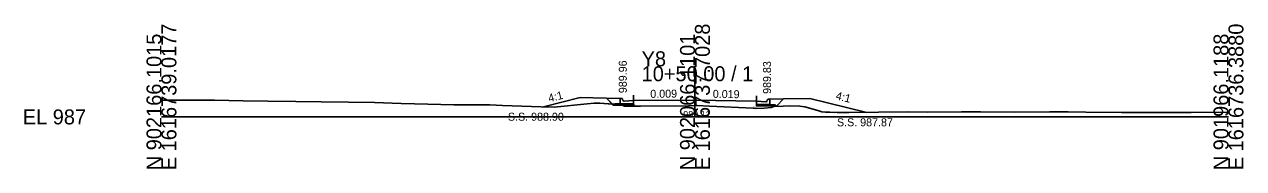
# Model space of a CAD drawing. Extents: x -26 to 1403, y -10 to 3025.
# Drawn here: x -25.7 to 202.8, y 490.3 to 517.3 of the extents above; entities that cross this region are included whole.
import ezdxf

# ---------------------------------------------------------------- set-up
doc = ezdxf.new("R2010")
doc.units = 0
for name, color, linetype in [('Exist Cross Section Cell', 7, 'Continuous'), ('Exist XS Center Line Elevation Label', 7, 'Continuous'), ('Exist XS Ground Line', 7, 'Continuous'), ('Prop XS Dump Level', 7, 'Continuous'), ('Prop XS Earthwork Shape', 7, 'Continuous'), ('Prop XS EOT Tick Mark', 7, 'Continuous'), ('Prop XS Finish Grade', 7, 'Continuous'), ('Prop XS Finish Grade CurbGutter', 7, 'Continuous'), ('Prop XS Finish Grade Earthwork', 7, 'Continuous'), ('Prop XS Finish Grade Pavement', 7, 'Continuous'), ('Prop XS Hydro Elevations', 7, 'Continuous'), ('Prop XS Pvmt Edge Slope', 7, 'Continuous'), ('Prop XS SE Text', 7, 'Continuous'), ('Prop XS Side Slope Text', 7, 'Continuous'), ('Prop XS SS Elevation Text', 7, 'Continuous'), ('Prop XS Subgrade CurbGutter', 7, 'Continuous'), ('Prop XS Subgrade Earthwork', 7, 'Continuous')]:
    doc.layers.add(name, color=color, linetype=linetype)

msp = doc.modelspace()

# ---------------------------------------------------------------- linework, layer by layer
at = {"layer": 'Exist Cross Section Cell'}
for p, q in [((100, 500), (100, 509.49)), ((0, 500), (100, 500)), ((100, 500), (200, 500))]:
    msp.add_line(p, q, dxfattribs=at)
at = {"layer": 'Exist XS Ground Line'}
for p, q in [((0, 503.16), (4.39, 503.14)), ((4.39, 503.14), (9.93, 503.11)), ((9.93, 503.11), (15.33, 503.04)), ((15.33, 503.04), (19.93, 502.97)), ((19.93, 502.97), (25.21, 502.91)), ((25.21, 502.91), (29.93, 502.83)), ((29.93, 502.83), (35.08, 502.76)), ((35.08, 502.76), (39.94, 502.68)), ((39.94, 502.68), (44.95, 502.54)), ((44.95, 502.54), (49.94, 502.41)), ((49.94, 502.41), (54.82, 502.28)), ((54.82, 502.28), (61.54, 502.23)), ((61.54, 502.23), (63.93, 502.13)), ((63.93, 502.13), (71.17, 501.91)), ((71.17, 501.91), (73.63, 501.83)), ((73.63, 501.83), (79.8, 502.47)), ((79.8, 502.47), (81.1, 502.58)), ((81.1, 502.58), (82.2, 502.56)), ((82.2, 502.56), (86.34, 502.26)), ((86.34, 502.26), (86.72, 502.04)), ((86.72, 502.04), (88.11, 501.99)), ((88.11, 501.99), (89.77, 502.02)), ((89.77, 502.02), (98.77, 502.1)), ((98.77, 502.1), (100, 502.11)), ((100, 502.11), (100.39, 502.11)), ((100.39, 502.11), (102.71, 502.02)), ((102.71, 502.02), (110.88, 501.61)), ((110.88, 501.61), (111.59, 501.59)), ((111.59, 501.59), (112.97, 501.61)), ((112.97, 501.61), (114.3, 501.78)), ((114.3, 501.78), (114.76, 501.96)), ((114.76, 501.96), (116.53, 502.01)), ((116.53, 502.01), (117.8, 502.1)), ((117.8, 502.1), (119.64, 502)), ((119.64, 502), (120.6, 501.88)), ((120.6, 501.88), (123.03, 501.2)), ((123.03, 501.2), (123.8, 500.95)), ((123.8, 500.95), (124.45, 500.88)), ((124.45, 500.88), (125.27, 500.89)), ((125.27, 500.89), (126.64, 500.85)), ((126.64, 500.85), (128.86, 500.84)), ((128.86, 500.84), (139.95, 500.93)), ((139.95, 500.93), (143.66, 500.88)), ((143.66, 500.88), (149.95, 500.92)), ((149.95, 500.92), (153.53, 500.92)), ((153.53, 500.92), (159.95, 500.86)), ((159.95, 500.86), (166.54, 500.93)), ((166.54, 500.93), (169.95, 500.92)), ((169.95, 500.92), (173.28, 500.89)), ((173.28, 500.89), (179.95, 500.82)), ((179.95, 500.82), (183.15, 500.84)), ((183.15, 500.84), (189.96, 500.8)), ((189.96, 500.8), (193.02, 500.81)), ((193.02, 500.81), (200, 500.9))]:
    msp.add_line(p, q, dxfattribs=at)
at = {"layer": 'Prop XS Dump Level'}
for p, q in [((100, 503.15), (88.47, 503.05)), ((100, 503.15), (88.47, 503.05)), ((111.51, 502.93), (100, 503.15)), ((111.51, 502.93), (100, 503.15))]:
    msp.add_line(p, q, dxfattribs=at)
at = {"layer": 'Prop XS Earthwork Shape'}
for points in [[(84.51, 502.4), (83.4, 503.5), (78.47, 503.61), (71.63, 501.9), (73.63, 501.83), (79.8, 502.47), (81.1, 502.58), (82.2, 502.56)], [(84.72, 502.18), (84.51, 502.4), (84.9, 502.37)], [(86.45, 502.2), (84.72, 502.18), (84.9, 502.37), (86.34, 502.26)]]:
    msp.add_lwpolyline(points, close=True, dxfattribs=at)
at = {"layer": 'Prop XS EOT Tick Mark'}
for p, q in [((88.47, 503.05), (88.47, 504.05)), ((111.51, 502.93), (111.51, 503.93))]:
    msp.add_line(p, q, dxfattribs=at)
at = {"layer": 'Prop XS Finish Grade'}
for p, q in [((85.97, 503.45), (83.4, 503.5)), ((114.01, 503.31), (116.59, 503.37))]:
    msp.add_line(p, q, dxfattribs=at)
at = {"layer": 'Prop XS Finish Grade CurbGutter'}
for p, q in [((85.97, 503.45), (86.22, 503.45)), ((86.22, 503.45), (86.34, 503.42)), ((86.44, 503.33), (86.34, 503.42)), ((86.5, 503.08), (86.44, 503.33)), ((86.59, 502.99), (86.5, 503.08)), ((86.72, 502.96), (86.59, 502.99)), ((88.47, 503.05), (86.72, 502.96)), ((111.51, 502.93), (113.26, 502.83)), ((113.26, 502.83), (113.38, 502.85)), ((113.38, 502.85), (113.47, 502.94)), ((113.47, 502.94), (113.54, 503.19)), ((113.54, 503.19), (113.63, 503.29)), ((113.76, 503.31), (113.63, 503.29)), ((114.01, 503.31), (113.76, 503.31))]:
    msp.add_line(p, q, dxfattribs=at)
at = {"layer": 'Prop XS Finish Grade Earthwork'}
for p, q in [((78.47, 503.61), (71.63, 501.9)), ((83.4, 503.5), (78.47, 503.61)), ((116.59, 503.37), (121.51, 503.47)), ((121.51, 503.47), (131.94, 500.86))]:
    msp.add_line(p, q, dxfattribs=at)
at = {"layer": 'Prop XS Finish Grade Pavement'}
for p, q in [((88.47, 503.05), (100, 503.15)), ((100, 503.15), (111.51, 502.93))]:
    msp.add_line(p, q, dxfattribs=at)
at = {"layer": 'Prop XS Pvmt Edge Slope'}
for p, q in [((84.97, 502.44), (84.72, 502.18)), ((85.97, 502.45), (84.97, 502.44)), ((114.01, 502.31), (115.01, 502.29)), ((115.01, 502.29), (115.26, 502.03))]:
    msp.add_line(p, q, dxfattribs=at)
at = {"layer": 'Prop XS Subgrade CurbGutter'}
for p, q in [((85.97, 502.45), (85.97, 503.45)), ((88.47, 503.05), (88.47, 502.47)), ((111.51, 502.93), (111.51, 502.35)), ((114.01, 502.31), (114.01, 503.31)), ((88.47, 502.47), (85.97, 502.45)), ((111.51, 502.35), (114.01, 502.31))]:
    msp.add_line(p, q, dxfattribs=at)
at = {"layer": 'Prop XS Subgrade Earthwork'}
for p, q in [((84.72, 502.18), (83.4, 503.5)), ((115.26, 502.03), (116.59, 503.37)), ((88.47, 502.22), (84.72, 502.18)), ((88.47, 502.47), (88.47, 502.22)), ((111.51, 502.35), (111.51, 502.1)), ((111.51, 502.1), (115.26, 502.03))]:
    msp.add_line(p, q, dxfattribs=at)

# ---------------------------------------------------------------- texts
at = {"layer": 'Exist Cross Section Cell'}
for s, p in [('E 1616739.0177', (2.8, 490)), ('E 1616737.7028', (102.8, 490)), ('E 1616736.3880', (202.8, 490)), ('N 902166.1015', (0, 490)), ('N 902066.1101', (100, 490)), ('N 901966.1188', (200, 490))]:
    msp.add_text(s, height=2.8, rotation=90, dxfattribs=at).set_placement(p)
for s, p in [('Y8', (90, 509.49)), ('10+50.00 / 1', (90, 506.69)), ('EL 987', (-26, 498.6))]:
    msp.add_text(s, height=2.8, dxfattribs=at).set_placement(p)
at = {"layer": 'Exist XS Center Line Elevation Label'}
msp.add_text('989.11', height=1.25, dxfattribs=at).set_placement((97.81, 499.85))
at = {"layer": 'Prop XS Dump Level'}
for p in [(88.11, 502.05), (110.88, 501.67)]:
    msp.add_text('Eop', height=0.3, dxfattribs=at).set_placement(p)
at = {"layer": 'Prop XS Hydro Elevations'}
for s, p in [('989.96', (87.22, 504.45)), ('989.83', (114.26, 504.31))]:
    msp.add_text(s, height=1.5, rotation=90, dxfattribs=at).set_placement(p)
at = {"layer": 'Prop XS SE Text'}
for s, rotation, p in [('0.009', 0.488, (91.63, 503.57)), ('0.019', 358.9391, (103.33, 503.58))]:
    msp.add_text(s, height=1.5, rotation=rotation, dxfattribs=at).set_placement(p)
at = {"layer": 'Prop XS Side Slope Text'}
for rotation, p in [(14.0362, (72.69, 502.74)), (345.9638, (126.29, 503.31))]:
    msp.add_text('4:1', height=1.5, rotation=rotation, dxfattribs=at).set_placement(p)
at = {"layer": 'Prop XS SS Elevation Text'}
for s, p in [('S.S. 988.90', (64.94, 499.28)), ('S.S. 987.87', (126.62, 498.24))]:
    msp.add_text(s, height=1.5, dxfattribs=at).set_placement(p)

doc.saveas('drawing.dxf')
